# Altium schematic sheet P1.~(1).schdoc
size 297 x 209 mm; Symbol: Drawing-Symbol_A4; Company: 嘉立创EDA; Version: V1.0; Page Size: A4; @Project Name: ADS1232; @Update Date: 2026-08-26; @Create Date: 2026-08-26; Device: Drawing-Symbol_A4; @Board Name: Board1; @Page Name: P1; @Create Time: 10:54:31; @Page Count: 1; @Page No: 1; @Schematic Name: Schematic1; @Update Time: 10:54:31; @Assembly Variant: Basic; Border: 1; Title Block Position: 3; Size: A4; Width: 1170; Height: 825; Region Start: 1; X Region Count: 6; Y Region Count: 4; Blade Width: 10
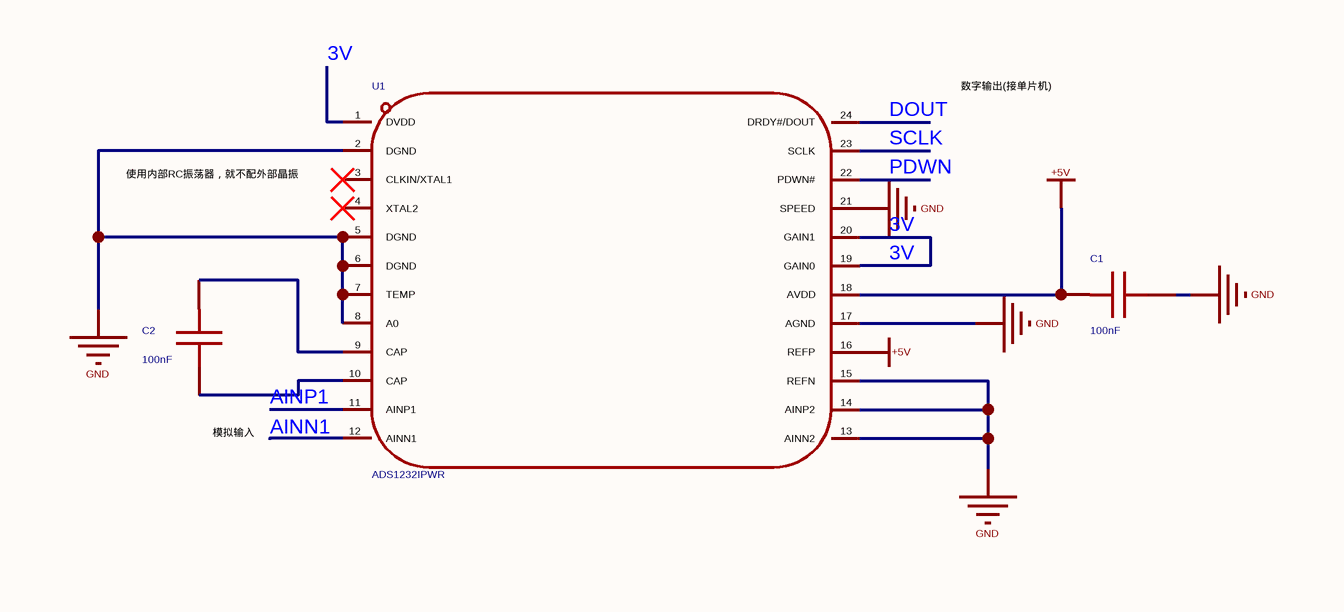
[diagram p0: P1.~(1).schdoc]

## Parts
C1  100nF  [C0603]
C2  100nF  [C0603]
U1  ADS1232IPWR  [TSSOP-24_L7.8-W4.4-P0.65-LS6.4-BL]

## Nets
+5V: C1.2 U1.16(REFP) U1.18(AVDD)
GND: C1.1 U1.2(DGND) U1.5(DGND) U1.6(DGND) U1.7(TEMP) U1.8(A0) U1.13(AINN2) U1.14(AINP2) U1.15(REFN) U1.17(AGND) U1.21(SPEED)
3V: U1.1(DVDD) U1.19(GAIN0) U1.20(GAIN1)
AINN1: U1.12(AINN1)
AINP1: U1.11(AINP1)
DOUT: U1.24(DRDY#/DOUT)
PDWN: U1.22(PDWN#)
SCLK: U1.23(SCLK)
NetC2_1: C2.1 U1.10(CAP)
NetC2_2: C2.2 U1.9(CAP)

Not connected (* = marked no-connect by the designer): U1 3(CLKIN/XTAL1)* 4(XTAL2)*

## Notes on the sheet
- 数字输出(接单片机)
- 使用内部RC振荡器，就不配外部晶振
- (near C2) 模拟输入

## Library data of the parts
C1 C2 = CAP_0603: Symbol: Capacitance; ConvertToPcb: yes; ModelId: ac125912035d415993ca9572d50418b1聨0819f05c4eef4c71ace90d822a990e87; ModelName: C0603_L1.6-W0.8-H0.8; ModelTransform: 62.992,31.496,0,0,0,0,0,0,0
U1 = ADS1232IPWR: 分辨率(位):24;采样率:10Hz;工作电压:2.7V~5.3V;接口类型:SPI;; Manufacturer: TI(德州仪器); AddInBom: yes; ModelId: 57e278220af748a2882c4abba4094eb9聨0819f05c4eef4c71ace90d822a990e87; ModelName: TSSOP-24_L7.8-W4.4-H1.0-LS6.4-P0.65; ModelTransform: 252.188,307.086,0,90,0,0,0,0,0; Resolution (Bits): 24; Sampling Rate: 10Hz; number of channels: 2; Interface: SPI; differential input: 是; Clock/Oscillator: 内置；外置; Clock Frequency: 4.9152MHz；200kHz~8MHz; Voltage Reference: 外置; Programmable Gain: 支持; Temperature Sensors: 内置; ADC architecture: Sigma-Delta; Data rate: 80Hz；10Hz; Quiescent Current (Iq): 1.3uA; Full-Scale Range(FSR): 39mV；1.25V；19.5mV；2.5V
